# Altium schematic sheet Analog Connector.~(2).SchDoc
size A
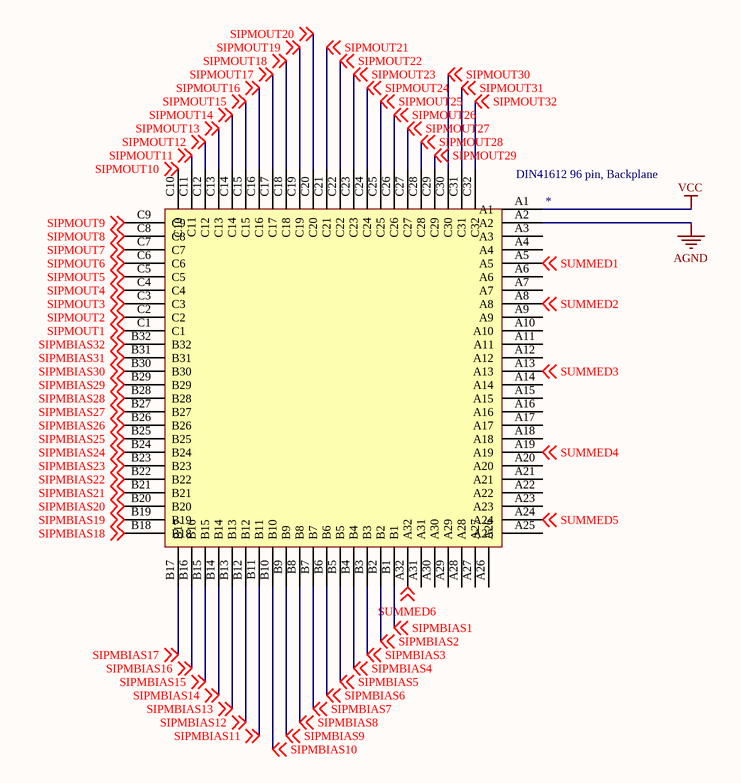
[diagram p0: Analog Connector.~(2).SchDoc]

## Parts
*  DIN41612 96 pin, Backplane  [EURO2.54-2V96]

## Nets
AGND: *.A2
VCC: *.A1
SIPMBIAS1: *.B1 ; off-sheet SIPMBIAS1
SIPMBIAS2: *.B2 ; off-sheet SIPMBIAS2
SIPMBIAS3: *.B3 ; off-sheet SIPMBIAS3
SIPMBIAS4: *.B4 ; off-sheet SIPMBIAS4
SIPMBIAS5: *.B5 ; off-sheet SIPMBIAS5
SIPMBIAS6: *.B6 ; off-sheet SIPMBIAS6
SIPMBIAS7: *.B7 ; off-sheet SIPMBIAS7
SIPMBIAS8: *.B8 ; off-sheet SIPMBIAS8
SIPMBIAS9: *.B9 ; off-sheet SIPMBIAS9
SIPMBIAS10: *.B10 ; off-sheet SIPMBIAS10
SIPMBIAS11: *.B11 ; off-sheet SIPMBIAS11
SIPMBIAS12: *.B12 ; off-sheet SIPMBIAS12
SIPMBIAS13: *.B13 ; off-sheet SIPMBIAS13
SIPMBIAS14: *.B14 ; off-sheet SIPMBIAS14
SIPMBIAS15: *.B15 ; off-sheet SIPMBIAS15
SIPMBIAS16: *.B16 ; off-sheet SIPMBIAS16
SIPMBIAS17: *.B17 ; off-sheet SIPMBIAS17
SIPMBIAS18: *.B18 ; off-sheet SIPMBIAS18
SIPMBIAS19: *.B19 ; off-sheet SIPMBIAS19
SIPMBIAS20: *.B20 ; off-sheet SIPMBIAS20
SIPMBIAS21: *.B21 ; off-sheet SIPMBIAS21
SIPMBIAS22: *.B22 ; off-sheet SIPMBIAS22
SIPMBIAS23: *.B23 ; off-sheet SIPMBIAS23
SIPMBIAS24: *.B24 ; off-sheet SIPMBIAS24
SIPMBIAS25: *.B25 ; off-sheet SIPMBIAS25
SIPMBIAS26: *.B26 ; off-sheet SIPMBIAS26
SIPMBIAS27: *.B27 ; off-sheet SIPMBIAS27
SIPMBIAS28: *.B28 ; off-sheet SIPMBIAS28
SIPMBIAS29: *.B29 ; off-sheet SIPMBIAS29
SIPMBIAS30: *.B30 ; off-sheet SIPMBIAS30
SIPMBIAS31: *.B31 ; off-sheet SIPMBIAS31
SIPMBIAS32: *.B32 ; off-sheet SIPMBIAS32
SIPMOUT1: *.C1 ; off-sheet SIPMOUT1
SIPMOUT2: *.C2 ; off-sheet SIPMOUT2
SIPMOUT3: *.C3 ; off-sheet SIPMOUT3
SIPMOUT4: *.C4 ; off-sheet SIPMOUT4
SIPMOUT5: *.C5 ; off-sheet SIPMOUT5
SIPMOUT6: *.C6 ; off-sheet SIPMOUT6
SIPMOUT7: *.C7 ; off-sheet SIPMOUT7
SIPMOUT8: *.C8 ; off-sheet SIPMOUT8
SIPMOUT9: *.C9 ; off-sheet SIPMOUT9
SIPMOUT10: *.C10 ; off-sheet SIPMOUT10
SIPMOUT11: *.C11 ; off-sheet SIPMOUT11
SIPMOUT12: *.C12 ; off-sheet SIPMOUT12
SIPMOUT13: *.C13 ; off-sheet SIPMOUT13
SIPMOUT14: *.C14 ; off-sheet SIPMOUT14
SIPMOUT15: *.C15 ; off-sheet SIPMOUT15
SIPMOUT16: *.C16 ; off-sheet SIPMOUT16
SIPMOUT17: *.C17 ; off-sheet SIPMOUT17
SIPMOUT18: *.C18 ; off-sheet SIPMOUT18
SIPMOUT19: *.C19 ; off-sheet SIPMOUT19
SIPMOUT20: *.C20 ; off-sheet SIPMOUT20
SIPMOUT21: *.C21 ; off-sheet SIPMOUT21
SIPMOUT22: *.C22 ; off-sheet SIPMOUT22
SIPMOUT23: *.C23 ; off-sheet SIPMOUT23
SIPMOUT24: *.C24 ; off-sheet SIPMOUT24
SIPMOUT25: *.C25 ; off-sheet SIPMOUT25
SIPMOUT26: *.C26 ; off-sheet SIPMOUT26
SIPMOUT27: *.C27 ; off-sheet SIPMOUT27
SIPMOUT28: *.C28 ; off-sheet SIPMOUT28
SIPMOUT29: *.C29 ; off-sheet SIPMOUT29
SIPMOUT30: *.C30 ; off-sheet SIPMOUT30
SIPMOUT31: *.C31 ; off-sheet SIPMOUT31
SIPMOUT32: *.C32 ; off-sheet SIPMOUT32
SUMMED1: *.A5 ; off-sheet SUMMED1
SUMMED2: *.A8 ; off-sheet SUMMED2
SUMMED3: *.A13 ; off-sheet SUMMED3
SUMMED4: *.A19 ; off-sheet SUMMED4
SUMMED5: *.A24 ; off-sheet SUMMED5
SUMMED6: *.A32 ; off-sheet SUMMED6

Not connected (* = marked no-connect by the designer): * A3 A4 A6 A7 A9 A10 A11 A12 A14 A15 A16 A17 A18 A20 A21 A22 A23 A25 A26 A27 A28 A29 A30 A31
